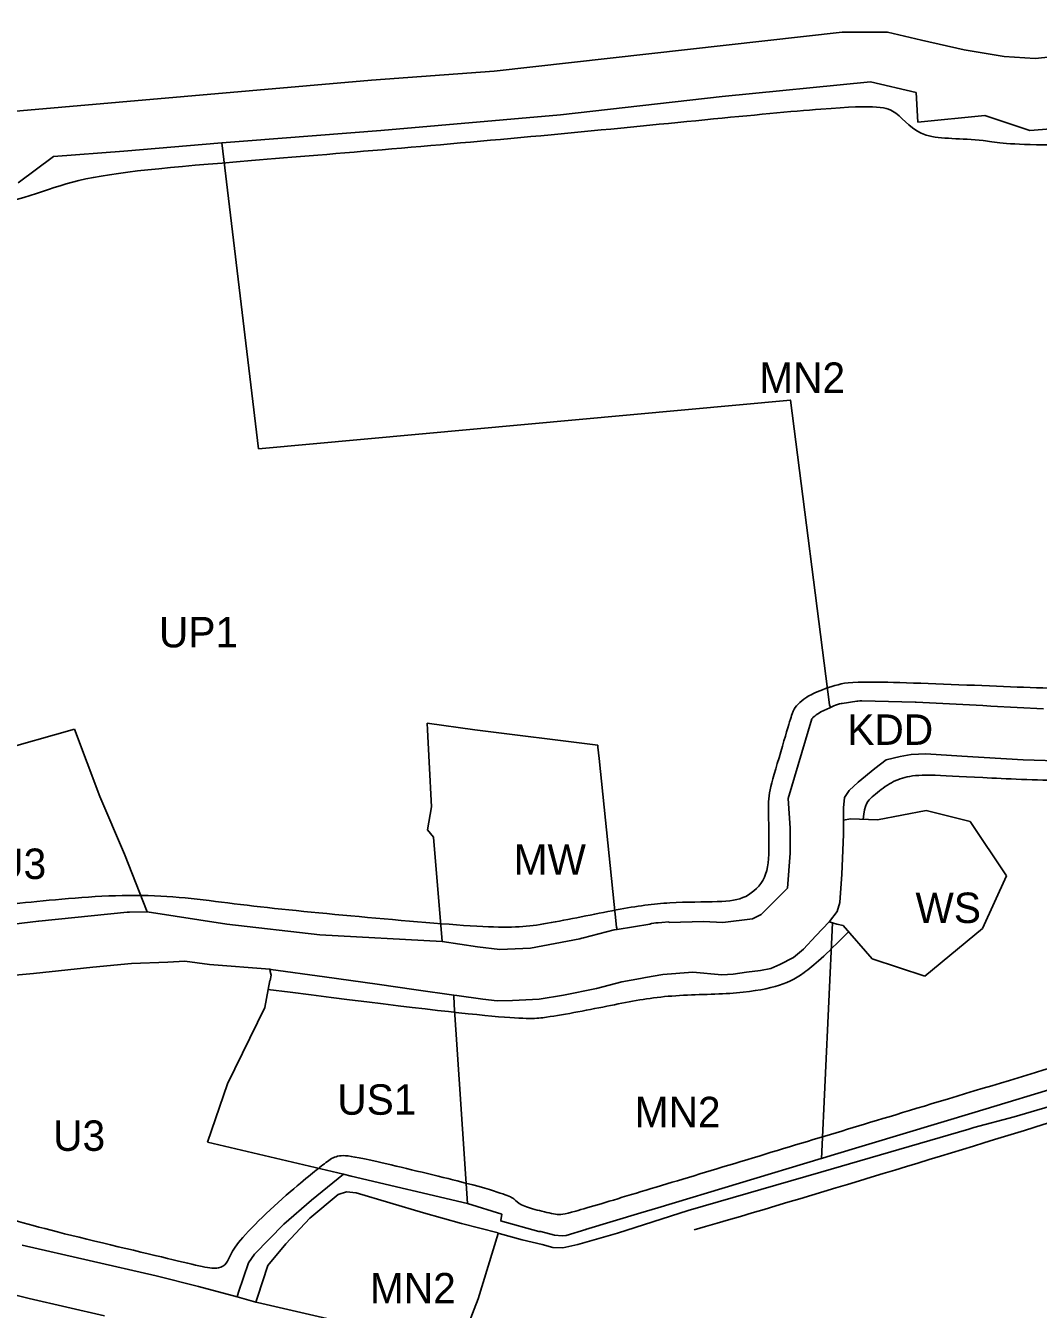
# Model space of a CAD drawing. Extents: x 7413438 to 7416393, y 5541665 to 5544118.
# Drawn here: x 7414442.9 to 7414642.6, y 5543026.2 to 5543279.3 of the extents above; entities that cross this region are included whole.
import ezdxf

# ---------------------------------------------------------------- set-up
doc = ezdxf.new("R2010")
doc.units = 0
for name, color, linetype in [('linie_rozgraniczajace', 7, 'Continuous'), ('linie_zabudowy_nieprzekraczalne', 7, 'Continuous'), ('oznaczenia_przeznaczen', 7, 'Continuous')]:
    doc.layers.add(name, color=color, linetype=linetype)

msp = doc.modelspace()

# ---------------------------------------------------------------- linework, layer by layer
at = {"layer": 'linie_rozgraniczajace'}
for p, q in [((7414707.33, 5543279.31), (7414641.96, 5543272.83)), ((7414603.93, 5543278.05), (7414535.29, 5543270.35)), ((7414612.85, 5543278), (7414603.93, 5543278.05)), ((7414619.57, 5543276.43), (7414612.85, 5543278)), ((7414627.95, 5543274.52), (7414619.57, 5543276.43)), ((7414635.89, 5543273.2), (7414627.95, 5543274.52)), ((7414641.96, 5543272.83), (7414635.89, 5543273.2)), ((7414535.29, 5543270.35), (7414511.08, 5543268.54)), ((7414511.08, 5543268.54), (7414427.62, 5543261.29)), ((7414580.27, 5543265.31), (7414609.48, 5543268.21)), ((7414609.48, 5543268.21), (7414618.53, 5543266.13)), ((7414548.38, 5543261.74), (7414580.27, 5543265.31)), ((7414618.53, 5543266.13), (7414618.85, 5543260.31)), ((7414512.92, 5543258.63), (7414548.38, 5543261.74)), ((7414618.85, 5543260.31), (7414632.07, 5543261.62)), ((7414632.07, 5543261.62), (7414640.94, 5543258.66)), ((7414618.85, 5543260.31), (7414618.85, 5543260.31)), ((7414640.94, 5543258.66), (7414665.43, 5543260.51)), ((7414481.54, 5543256.19), (7414486.71, 5543256.62)), ((7414486.71, 5543256.62), (7414512.92, 5543258.63)), ((7414448.36, 5543253.51), (7414462.25, 5543254.59)), ((7414462.25, 5543254.59), (7414481.54, 5543256.19)), ((7414488.79, 5543195.84), (7414481.54, 5543256.19)), ((7414441.38, 5543248.29), (7414448.36, 5543253.51)), ((7414593.76, 5543205.46), (7414488.79, 5543195.84)), ((7414601.44, 5543145.39), (7414593.76, 5543205.46)), ((7414593.76, 5543205.46), (7414593.77, 5543205.46)), ((7414593.77, 5543205.46), (7414593.76, 5543205.46)), ((7414601.59, 5543144.86), (7414601.44, 5543145.39)), ((7414602.16, 5543145.14), (7414601.59, 5543144.86)), ((7414602.25, 5543145.18), (7414602.16, 5543145.14)), ((7414602.61, 5543145.33), (7414602.25, 5543145.18)), ((7414602.98, 5543145.46), (7414602.61, 5543145.33)), ((7414603.36, 5543145.57), (7414602.98, 5543145.46)), ((7414603.74, 5543145.65), (7414603.36, 5543145.57)), ((7414603.89, 5543145.67), (7414603.74, 5543145.65)), ((7414606.78, 5543146.09), (7414603.89, 5543145.67)), ((7414607.01, 5543146.12), (7414606.78, 5543146.09)), ((7414607.41, 5543146.15), (7414607.01, 5543146.12)), ((7414607.77, 5543146.16), (7414607.41, 5543146.15)), ((7414618.31, 5543145.94), (7414607.77, 5543146.16)), ((7414618.34, 5543145.94), (7414618.31, 5543145.94)), ((7414618.51, 5543145.94), (7414618.34, 5543145.94)), ((7414631.64, 5543145.24), (7414618.51, 5543145.94)), ((7414633.27, 5543145.15), (7414631.64, 5543145.24)), ((7414643.66, 5543144.59), (7414633.27, 5543145.15)), ((7414593.28, 5543126.89), (7414597.93, 5543142.63)), ((7414597.93, 5543142.64), (7414597.95, 5543142.65)), ((7414597.93, 5543142.63), (7414597.93, 5543142.64)), ((7414597.95, 5543142.65), (7414597.97, 5543142.68)), ((7414597.97, 5543142.68), (7414598.1, 5543142.82)), ((7414598.1, 5543142.82), (7414598.22, 5543142.92)), ((7414598.22, 5543142.92), (7414598.5, 5543143.17)), ((7414598.5, 5543143.17), (7414598.81, 5543143.41)), ((7414598.81, 5543143.41), (7414599.14, 5543143.64)), ((7414599.14, 5543143.64), (7414599.48, 5543143.83)), ((7414599.48, 5543143.83), (7414599.74, 5543143.97)), ((7414599.74, 5543143.97), (7414601.5, 5543144.82)), ((7414601.5, 5543144.82), (7414601.59, 5543144.86)), ((7414432.13, 5543134.79), (7414452.48, 5543140.56)), ((7414452.48, 5543140.56), (7414457.53, 5543127.32)), ((7414522.13, 5543140.42), (7414522.05, 5543141.74)), ((7414522.05, 5543141.74), (7414531.5, 5543140.42)), ((7414522.45, 5543134.09), (7414522.13, 5543140.42)), ((7414531.5, 5543140.42), (7414555.72, 5543137.44)), ((7414555.72, 5543137.44), (7414555.76, 5543137.01)), ((7414555.76, 5543137.01), (7414556, 5543134.78)), ((7414612.58, 5543134.56), (7414615.36, 5543135.19)), ((7414615.36, 5543135.19), (7414617.5, 5543135.58)), ((7414617.5, 5543135.58), (7414620.45, 5543135.7)), ((7414620.45, 5543135.7), (7414627.5, 5543135.24)), ((7414627.5, 5543135.24), (7414639.6, 5543134.55)), ((7414522.91, 5543125.28), (7414522.45, 5543134.09)), ((7414556, 5543134.78), (7414559.44, 5543101.51)), ((7414607.06, 5543130.12), (7414610.35, 5543132.84)), ((7414610.35, 5543132.84), (7414612.58, 5543134.56)), ((7414639.6, 5543134.55), (7414649.9, 5543134.23)), ((7414605.27, 5543128.49), (7414607.06, 5543130.12)), ((7414457.53, 5543127.32), (7414462.4, 5543115.94)), ((7414604.37, 5543127.12), (7414605.27, 5543128.49)), ((7414522.16, 5543120.72), (7414522.91, 5543125.28)), ((7414593.64, 5543121.05), (7414593.28, 5543126.89)), ((7414604.15, 5543122.61), (7414604.16, 5543125.04)), ((7414604.16, 5543125.04), (7414604.37, 5543127.12)), ((7414604.15, 5543122.61), (7414605.55, 5543122.91)), ((7414604.15, 5543119.79), (7414604.15, 5543122.61)), ((7414605.55, 5543122.91), (7414610.86, 5543122.73)), ((7414610.86, 5543122.73), (7414620.48, 5543124.54)), ((7414620.48, 5543124.54), (7414629.15, 5543122.36)), ((7414629.15, 5543122.36), (7414636.35, 5543111.65)), ((7414523.31, 5543119.3), (7414522.16, 5543120.72)), ((7414593.64, 5543119.29), (7414593.64, 5543121.05)), ((7414603.87, 5543112), (7414604.15, 5543119.79)), ((7414525.02, 5543098.72), (7414523.31, 5543119.3)), ((7414593.63, 5543116.62), (7414593.64, 5543119.29)), ((7414462.4, 5543115.94), (7414466.84, 5543104.59)), ((7414593.13, 5543109.2), (7414593.63, 5543116.16)), ((7414593.63, 5543116.16), (7414593.63, 5543116.62)), ((7414603.43, 5543106.43), (7414603.87, 5543112)), ((7414636.35, 5543111.65), (7414631.62, 5543101.26)), ((7414587.91, 5543104.04), (7414593.13, 5543109.2)), ((7414462.92, 5543104.47), (7414445.5, 5543102.73)), ((7414463.27, 5543104.49), (7414462.92, 5543104.47)), ((7414463.35, 5543104.49), (7414463.27, 5543104.49)), ((7414466.84, 5543104.59), (7414463.35, 5543104.49)), ((7414466.84, 5543104.59), (7414482.53, 5543102.15)), ((7414601.44, 5543102.65), (7414602.91, 5543104.64)), ((7414602.91, 5543104.64), (7414603.43, 5543106.43)), ((7414445.41, 5543102.72), (7414436.75, 5543101.72)), ((7414445.46, 5543102.73), (7414445.41, 5543102.72)), ((7414445.5, 5543102.73), (7414445.46, 5543102.73)), ((7414482.53, 5543102.15), (7414500.87, 5543100.04)), ((7414559.52, 5543101.09), (7414565.98, 5543102.14)), ((7414565.98, 5543102.14), (7414566.1, 5543102.21)), ((7414566.1, 5543102.21), (7414566.28, 5543102.23)), ((7414566.28, 5543102.23), (7414566.39, 5543102.26)), ((7414566.39, 5543102.26), (7414566.78, 5543102.34)), ((7414566.78, 5543102.34), (7414567.17, 5543102.39)), ((7414567.17, 5543102.39), (7414567.56, 5543102.42)), ((7414567.56, 5543102.42), (7414567.65, 5543102.42)), ((7414567.65, 5543102.42), (7414568.32, 5543102.44)), ((7414568.32, 5543102.44), (7414569.71, 5543102.58)), ((7414569.71, 5543102.58), (7414569.8, 5543102.48)), ((7414569.8, 5543102.48), (7414576.57, 5543102.63)), ((7414576.57, 5543102.63), (7414580.4, 5543102.45)), ((7414580.4, 5543102.45), (7414586.21, 5543103.2)), ((7414586.21, 5543103.2), (7414587.91, 5543104.04)), ((7414598.74, 5543099.8), (7414601.36, 5543102.57)), ((7414602.02, 5543102.38), (7414599.84, 5543055.88)), ((7414601.36, 5543102.57), (7414601.44, 5543102.65)), ((7414602.02, 5543102.38), (7414601.36, 5543102.57)), ((7414602.85, 5543102.15), (7414602.02, 5543102.38)), ((7414604.13, 5543101.86), (7414602.85, 5543102.15)), ((7414500.87, 5543100.04), (7414525.02, 5543098.72)), ((7414552.89, 5543099.45), (7414552.58, 5543099.36)), ((7414552.91, 5543099.44), (7414552.89, 5543099.45)), ((7414558.92, 5543101), (7414552.91, 5543099.44)), ((7414559.52, 5543101.09), (7414558.92, 5543101)), ((7414559.44, 5543101.51), (7414559.52, 5543101.09)), ((7414596.26, 5543097.18), (7414598.74, 5543099.8)), ((7414609.85, 5543095.32), (7414604.13, 5543101.86)), ((7414631.62, 5543101.26), (7414620.19, 5543091.9)), ((7414532.01, 5543097.67), (7414525.02, 5543098.72)), ((7414536.39, 5543097.14), (7414532.01, 5543097.67)), ((7414542.48, 5543097.41), (7414536.39, 5543097.14)), ((7414552.19, 5543099.26), (7414542.48, 5543097.41)), ((7414552.58, 5543099.36), (7414552.19, 5543099.26)), ((7414594.32, 5543095.55), (7414596.26, 5543097.18)), ((7414456.13, 5543093.64), (7414463.72, 5543094.4)), ((7414463.72, 5543094.4), (7414470.89, 5543094.61)), ((7414470.89, 5543094.61), (7414474.29, 5543094.83)), ((7414474.29, 5543094.83), (7414479.13, 5543094.21)), ((7414591.64, 5543094.18), (7414594.32, 5543095.55)), ((7414620.19, 5543091.9), (7414609.85, 5543095.32)), ((7414431.53, 5543091.27), (7414444.41, 5543092.43)), ((7414444.41, 5543092.43), (7414456.13, 5543093.64)), ((7414479.13, 5543094.21), (7414491.06, 5543093.23)), ((7414491.13, 5543092.83), (7414491.06, 5543093.23)), ((7414491.06, 5543093.23), (7414491.23, 5543093.22)), ((7414491.08, 5543091.03), (7414491.3, 5543092.07)), ((7414491.3, 5543092.07), (7414491.13, 5543092.83)), ((7414491.23, 5543093.22), (7414501.8, 5543091.72)), ((7414565.1, 5543091.61), (7414568.55, 5543092.21)), ((7414568.55, 5543092.21), (7414574.45, 5543092.67)), ((7414574.45, 5543092.67), (7414580.17, 5543092.16)), ((7414580.17, 5543092.16), (7414582.39, 5543092.25)), ((7414582.39, 5543092.25), (7414585.04, 5543092.66)), ((7414585.04, 5543092.66), (7414587.84, 5543092.99)), ((7414587.84, 5543092.99), (7414589.82, 5543093.37)), ((7414589.82, 5543093.37), (7414591.64, 5543094.18)), ((7414490.04, 5543085.72), (7414491.05, 5543091.03)), ((7414491.05, 5543091.03), (7414491.08, 5543091.03)), ((7414501.8, 5543091.72), (7414512.22, 5543090.3)), ((7414512.22, 5543090.3), (7414519.89, 5543089.2)), ((7414548.95, 5543088.16), (7414555.49, 5543089.46)), ((7414555.49, 5543089.46), (7414560.47, 5543090.77)), ((7414560.47, 5543090.77), (7414564.14, 5543091.44)), ((7414564.14, 5543091.44), (7414565.1, 5543091.61)), ((7414519.89, 5543089.2), (7414527.31, 5543088.14)), ((7414527.41, 5543086.23), (7414527.31, 5543088.14)), ((7414527.31, 5543088.14), (7414527.93, 5543088.05)), ((7414527.93, 5543088.05), (7414533.07, 5543087.37)), ((7414533.07, 5543087.37), (7414535.9, 5543087.04)), ((7414535.9, 5543087.04), (7414538.93, 5543087.09)), ((7414538.93, 5543087.09), (7414544.17, 5543087.37)), ((7414544.17, 5543087.37), (7414548.95, 5543088.16)), ((7414482.66, 5543070.63), (7414490.04, 5543085.72)), ((7414530.04, 5543047.02), (7414527.41, 5543086.23)), ((7414630.15, 5543065.09), (7414661.06, 5543074.48)), ((7414478.72, 5543059.15), (7414482.66, 5543070.63)), ((7414654.32, 5543068.97), (7414637.83, 5543064.13)), ((7414601.75, 5543056.54), (7414630.15, 5543065.09)), ((7414637.83, 5543064.13), (7414629.89, 5543062.02)), ((7414628.89, 5543061.68), (7414599.72, 5543053.25)), ((7414629.89, 5543062.02), (7414628.89, 5543061.68)), ((7414505.56, 5543052.81), (7414478.72, 5543059.15)), ((7414599.85, 5543055.89), (7414601.75, 5543056.54)), ((7414599.77, 5543055.89), (7414567.57, 5543046.21)), ((7414599.84, 5543055.88), (7414599.77, 5543055.89)), ((7414599.84, 5543055.88), (7414599.85, 5543055.89)), ((7414599.84, 5543055.88), (7414599.84, 5543055.88)), ((7414499.24, 5543047.73), (7414505.56, 5543052.81)), ((7414507.1, 5543052.45), (7414505.56, 5543052.81)), ((7414530.04, 5543047.02), (7414507.1, 5543052.45)), ((7414599.72, 5543053.25), (7414573.52, 5543045.69)), ((7414498.91, 5543044.16), (7414504.51, 5543048.8)), ((7414504.51, 5543048.8), (7414506.15, 5543049.35)), ((7414506.15, 5543049.35), (7414508.07, 5543049.13)), ((7414508.07, 5543049.13), (7414521.35, 5543045.19)), ((7414493.77, 5543042.97), (7414499.24, 5543047.73)), ((7414536.81, 5543044.92), (7414530.04, 5543047.02)), ((7414494.17, 5543039.08), (7414498.91, 5543044.16)), ((7414521.35, 5543045.19), (7414528.83, 5543043.11)), ((7414536.56, 5543043.65), (7414536.58, 5543043.72)), ((7414536.58, 5543043.72), (7414536.81, 5543044.92)), ((7414564.24, 5543045.2), (7414553.32, 5543041.92)), ((7414573.53, 5543045.67), (7414559.63, 5543041.2)), ((7414567.57, 5543046.21), (7414564.24, 5543045.2)), ((7414573.52, 5543045.69), (7414573.53, 5543045.67)), ((7414487.98, 5543037.07), (7414493.77, 5543042.97)), ((7414528.83, 5543043.11), (7414536.1, 5543041.27)), ((7414536.1, 5543041.27), (7414536.08, 5543041.14)), ((7414544.09, 5543041.5), (7414536.56, 5543043.65)), ((7414544.46, 5543041.52), (7414544.09, 5543041.5)), ((7414547.18, 5543040.81), (7414544.46, 5543041.52)), ((7414553.37, 5543041.92), (7414549.45, 5543040.73)), ((7414559.63, 5543041.2), (7414551.79, 5543038.97)), ((7414553.32, 5543041.92), (7414553.37, 5543041.92)), ((7414468.63, 5543032.8), (7414442.16, 5543038.85)), ((7414490.64, 5543034.85), (7414494.17, 5543039.08)), ((7414536.08, 5543041.14), (7414532.11, 5543028.28)), ((7414536.25, 5543041.15), (7414536.08, 5543041.14)), ((7414540.83, 5543039.9), (7414536.25, 5543041.15)), ((7414544.75, 5543038.99), (7414540.83, 5543039.9)), ((7414546.86, 5543038.36), (7414544.75, 5543038.99)), ((7414548.67, 5543040.7), (7414547.18, 5543040.81)), ((7414549.45, 5543040.73), (7414548.67, 5543040.7)), ((7414551.79, 5543038.97), (7414548.83, 5543038.32)), ((7414486.86, 5543035.35), (7414487.98, 5543037.07)), ((7414548.83, 5543038.32), (7414546.86, 5543038.36)), ((7414484.85, 5543029.59), (7414486.86, 5543035.35)), ((7414488.63, 5543028.56), (7414490.64, 5543034.85)), ((7414476.98, 5543030.69), (7414468.63, 5543032.8)), ((7414439.11, 5543029.46), (7414443.55, 5543028.29)), ((7414484.61, 5543028.62), (7414476.98, 5543030.69)), ((7414484.61, 5543028.62), (7414484.85, 5543029.59)), ((7414488.3, 5543027.62), (7414484.61, 5543028.62)), ((7414488.3, 5543027.62), (7414488.63, 5543028.56)), ((7414443.55, 5543028.29), (7414458.42, 5543024.91)), ((7414488.62, 5543027.53), (7414488.3, 5543027.62)), ((7414509.98, 5543022.6), (7414488.62, 5543027.53)), ((7414532.11, 5543028.28), (7414527.96, 5543017.46))]:
    msp.add_line(p, q, dxfattribs=at)
at = {"layer": 'linie_zabudowy_nieprzekraczalne'}
for points in [[(7414687.23, 5543257.54), (7414640.54, 5543254.67), (7414631.57, 5543257.54), (7414619.22, 5543256.49), (7414614.66, 5543262.9), (7414609.18, 5543264.16), (7414546.97, 5543257.6), (7414481.96, 5543252.26), (7414449.78, 5543249.6), (7414442.77, 5543244.55), (7414429.85, 5543242.9)], [(7414799.65, 5543182.56), (7414796.22, 5543180.46), (7414791.68, 5543177.37), (7414781.93, 5543169.49), (7414769.91, 5543160.14), (7414761.92, 5543154.35), (7414757.12, 5543151.05), (7414750.78, 5543147.55), (7414739.82, 5543141.5), (7414733.49, 5543138.64), (7414727.52, 5543136.56), (7414718.03, 5543134.11), (7414709.3, 5543132.88), (7414685.58, 5543131.07), (7414666.16, 5543130.53), (7414647.72, 5543130.28), (7414630.48, 5543131.05), (7414620.36, 5543131.68), (7414616.12, 5543131.26), (7414612.81, 5543129.71), (7414609.64, 5543127.09), (7414608.29, 5543125.86), (7414608.06, 5543122.81)], [(7414341.07, 5543163.28), (7414356.51, 5543147.6), (7414375.53, 5543125.83), (7414392.4, 5543108.91), (7414398.25, 5543103.17), (7414401.25, 5543100.02), (7414408.23, 5543099.78), (7414415, 5543102.86), (7414429.11, 5543104.87), (7414443.72, 5543106.55), (7414466.68, 5543108.58), (7414484.3, 5543105.95), (7414507.74, 5543103.66), (7414536.5, 5543101.14), (7414544.43, 5543101.85), (7414560.45, 5543105.29), (7414569.76, 5543106.57), (7414580.19, 5543106.45), (7414585, 5543107.07), (7414589.21, 5543110.97), (7414589.59, 5543117.25), (7414589.25, 5543126.63), (7414589.81, 5543129.39), (7414593.09, 5543140.49), (7414594.13, 5543144.01), (7414594.78, 5543145.14), (7414596.31, 5543146.56), (7414597.95, 5543147.56), (7414603.22, 5543149.61), (7414607.81, 5543150.14), (7414636.45, 5543148.97), (7414652.66, 5543148.29), (7414679.53, 5543149.04), (7414698.29, 5543150.16)], [(7414431.95, 5543087.28), (7414424.23, 5543086.19), (7414420.06, 5543085.34), (7414419, 5543080.42), (7414421.28, 5543073.71), (7414423.39, 5543062.01), (7414425.39, 5543058.29), (7414430.81, 5543048.92), (7414433.87, 5543045.88), (7414444.69, 5543042.35), (7414474.63, 5543035.39), (7414481.89, 5543033.43), (7414483.16, 5543036.96), (7414485.08, 5543039.86), (7414490.96, 5543045.85), (7414497.7, 5543051.64), (7414500.63, 5543053.95), (7414503, 5543055.91), (7414505.09, 5543056.77), (7414509.77, 5543055.9), (7414530.22, 5543051.06), (7414537.37, 5543048.9), (7414539.27, 5543048.01), (7414540.33, 5543046.71), (7414543.6, 5543045.77), (7414547.8, 5543044.76), (7414549.47, 5543044.91), (7414562.64, 5543048.9), (7414579.93, 5543054.1), (7414600, 5543060.19), (7414616.25, 5543065.09), (7414646.94, 5543074.37), (7414667.99, 5543080.68), (7414683.48, 5543085.15), (7414703.27, 5543094.8), (7414711.92, 5543099.17), (7414719.64, 5543105.12), (7414735.49, 5543119.82), (7414750.36, 5543133.73), (7414756.76, 5543139.86), (7414758.13, 5543140.61), (7414759.94, 5543140.74), (7414761.63, 5543140.06), (7414763.36, 5543138.3), (7414765.4, 5543135.79), (7414765.75, 5543133.75), (7414763.94, 5543132.46), (7414737.28, 5543107.58), (7414725.35, 5543096.6), (7414718.45, 5543091.83), (7414705.59, 5543084.52), (7414694.22, 5543079.04), (7414682.4, 5543074.49), (7414654.76, 5543066.06), (7414598.61, 5543048.77), (7414574.71, 5543041.85)], [(7414605.15, 5543100.63), (7414600.53, 5543095.91), (7414596.1, 5543091.98), (7414591.41, 5543089.71), (7414582.51, 5543088.25), (7414569.01, 5543088.23), (7414558.99, 5543086.25), (7414544.55, 5543083.38), (7414539.04, 5543083.08), (7414490.67, 5543089.25)]]:
    msp.add_open_spline(points, degree=3, dxfattribs=at)

# ---------------------------------------------------------------- texts
at = {"layer": 'oznaczenia_przeznaczen'}
for s, p in [('MN2', (7414587.56, 5543206.9)), ('UP1', (7414469.17, 5543156.71)), ('KDD', (7414604.93, 5543137.49)), ('U3', (7414436.68, 5543111.04)), ('MW', (7414539.12, 5543111.86)), ('WS', (7414618.37, 5543102.36)), ('US1', (7414504.34, 5543064.55)), ('MN2', (7414562.99, 5543062.09)), ('U3', (7414448.3, 5543057.43)), ('MN2', (7414510.77, 5543027.35))]:
    msp.add_text(s, height=6, dxfattribs=at).set_placement(p)

doc.saveas('drawing.dxf')
